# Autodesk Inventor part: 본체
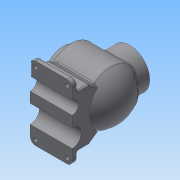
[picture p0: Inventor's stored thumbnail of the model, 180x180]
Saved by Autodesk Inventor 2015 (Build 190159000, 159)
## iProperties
Created: 2018-08
Part Number: 본체
Material: 일반
Document SubType Name: Modeling
Designer: user
Density: 1 g/cm^3
Appearance: 기본값
Mass: 665.121 g
Surface Area: 1060.85 cm^2
Volume: 665.121 cm^3
Author: user
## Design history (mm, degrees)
sketch "스케치1"
  geometry: 1 further point
sketch "스케치2"
  geometry: L1 (0, 0)-(120, 0); L2 (0, 0)-(0, 38); L3 (0, 38)-(12, 38); L4 (12, 38)-(12, 50); L5 (12, 50)-(91.394, 50); A1 r 58 centre (62, 0) between (120, 0) and (91.394, 50)
  constraints: 10 end point, 2 horizontal, 2 perpendicular, 2 point on circle, 1 centre point, 1 horizontal alignment, 1 vertical
  dimensions: "d1" = 38 distance of L1.start L2.end; "d2" = 12 distance of L2.end L3.end; "d7" = 50 distance between parallel lines of L1 L5; "d10" = 116 diameter of A1; "d11" = 108 horizontal distance of L1.end L4.end
revolve "회전1" sketch "스케치2" stored, may be unused: angle "d12" = 90 deg
node "작업 평면1"
sketch "스케치5"
  geometry: L1 (0, 0)-(-82, 0); L2 (-73.171, -50)-(-73.171, -70); L3 (-73.171, -70)-(-83.171, -70); L4 (-83.171, -70)-(-83.171, 70); L5 (-83.171, 70)-(-73.171, 70); L6 (-73.171, 70)-(-73.171, 50); L7 (-73.171, 50)-(-50.839, 50); L8 (-50.839, 50)-(-33.034, 37.533); L9 (-33.034, -37.533)-(-50.839, -50); L10 (-50.839, -50)-(-73.171, -50); A1 r 50 centre (0, 0) between (-33.034, 37.533) and (-33.034, -37.533) reference; A2 r 50 centre (0, 0) between (-33.034, 37.533) and (-33.034, -37.533); 1 further point
  constraints: 20 end point, 4 perpendicular, 4 point on circle, 3 horizontal, 3 horizontal alignment, 1 centre point, 1 coincident, 1 midpoint, 1 vertical alignment, 1 other
  dimensions: "d42" = 82 distance of L1.start L1.end; "d43" = 10 distance of L4.end L5.end; "d44" = 10 distance of L2.end L3.end; "d45" = 140 distance of L3.end L4.end; "d46" = 20 distance of L2.start L2.end; "d47" = 20 distance of L5.end L6.end; "d48" = 35 deg angle of L3 L9
extrude "돌출1" join sketch "스케치5" stored distance "d49" = 80; taper "d50" = 0 deg
sketch "스케치6"
  geometry: L1 (-50, -73.171)-(-70, -73.171) reference; L2 (-70, -73.171)-(-70, -83.171) reference; L3 (-70, -83.171)-(70, -83.171) reference; L4 (70, -83.171)-(70, -73.171) reference; L5 (70, -73.171)-(50, -73.171) reference; L6 (0, 0)-(0, -83.171); C1 r 38 at (0, 0) reference; C2 r 17.5 at (-22.5, -83.171); C3 r 12.5 at (27.5, -83.171); 1 further point
  constraints: 2 centre point, 2 end point, 2 midpoint, 2 point on line, 1 horizontal alignment
  dimensions: "d51" = 35 diameter of C2; "d53" = 22.5 distance of C2.centre L6.end; "d55" = 25 diameter of C3; "d56" = 27.5 distance of C3.centre L6.end
extrude "돌출2" cut sketch "스케치6" stored distance "d57" = 80; taper "d58" = 0 deg
sketch "스케치8"
  geometry: L1 (-12, -50)-(-91.394, -50) reference; L2 (0, 38)-(0, -38) reference; L3 (0, 38)-(0, -38) reference; L4 (-12, 38)-(-12, -38) reference; L5 (-91.394, -37.533)-(-91.394, 37.533) reference; L6 (-91.394, 37.533)-(-91.394, -37.533) reference; L7 (-20, 37.533)-(-91.394, 37.533) reference; L8 (-91.394, -37.533)-(-91.394, 37.533) reference; L9 (-91.394, -37.533)-(-20, -37.533) reference; L10 (-20, -37.533)-(-20, 37.533) reference; L11 (-12, 50)-(-12, -50) reference; C1 r 38 at (-62, 0); 2 further points
  constraints: 1 centre point, 1 horizontal alignment, 1 midpoint
  dimensions: "d59" = 76 diameter of C1; "d60" = 50 distance from line of L4 C1.centre
extrude "돌출3" join sketch "스케치8" distance "d61" = 65; taper "d62" = 0 deg
sketch "스케치9"
  geometry: L1 (0, -38)-(0, 38) reference; L2 (12, -38)-(12, 38) reference; L3 (91.394, 43.818)-(91.394, 43.818) reference; L4 (91.394, 43.818)-(91.394, -33.034) reference; L5 (91.394, -33.034)-(91.394, -33.034) reference; L6 (91.394, -33.034)-(91.394, 43.818) reference; L7 (0, 0)-(110, 0); L8 (0, 0)-(0, 27); L9 (0, 27)-(22, 27); L10 (22, 27)-(22, 40); L11 (22, 40)-(88.533, 40); A1 r 58 centre (62, 0) between (91.394, -50) and (100, 43.818) reference; A2 r 48 centre (62, 0) between (110, 0) and (88.533, 40)
  constraints: 10 end point, 3 perpendicular, 2 point on circle, 1 centre point, 1 horizontal, 1 point on line
  dimensions: "d63" = 27 distance of L7.start L8.end; "d64" = 22 distance of L8.end L9.end; "d65" = 10 radial gap between concentric circles of A1 A2; "d66" = 40 distance between parallel lines of L7 L11
revolve "회전2" sketch "스케치9" stored, may be unused: angle "d67" = 90 deg
sketch "스케치10"
  geometry: C1 r 38 at (0, 0) reference; C2 r 27 at (0, 0); 1 further point
  constraints: 1 centre point, 1 coincident
  dimensions: "d68" = 54 diameter of C2
extrude "돌출4" cut sketch "스케치10" stored distance "d69" = 65; taper "d70" = 0 deg
sketch "스케치11"
  geometry: C1 r 27 at (0, 0) reference; 2 further points
  constraints: 1 horizontal alignment
  dimensions: "d71" = 32.5 distance of point (-32.5, 0) C1.centre
hole "구멍1" sketch "스케치11" at (-32.5, 0) diameter "d72" = 3.242; stored, may be unused: countersink angle "d76" = 90 deg, drill point angle "d78" = 118 deg; dims "d73" = 8, "d74" = 4, "d75" = 2, "d77" = 10
sketch "스케치12"
  geometry: C1 r 27 at (0, 0) reference; 1 further point
  constraints: 1 vertical alignment
  dimensions: "d82" = 32.5 distance of C1.centre point (0, 32.5)
hole "구멍2" sketch "스케치12" at (0, 32.5) diameter "d83" = 3.242; stored, may be unused: countersink angle "d87" = 90 deg, drill point angle "d89" = 118 deg; dims "d84" = 8, "d85" = 4, "d86" = 2, "d88" = 10
sketch "스케치13"
  geometry: L1 (0, 0)-(0, 20) reference; C1 r 4 at (10, 10); C2 r 4 at (70, 10); 2 further points
  constraints: 2 centre point
  dimensions: "d93" = 8 diameter of C1; "d94" = 10 distance from line of L1 C1.centre; "d95" = 10 horizontal distance of L1.end C1.centre; "d96" = 8 diameter of C2; "d97" = 10 horizontal distance of point (80, 20) C2.centre; "d98" = 10 horizontal distance of point (80, 20) C2.centre
extrude "돌출5" cut sketch "스케치13" stored distance "d99" = 65; taper "d100" = 0 deg
node "작업 평면2"
sketch "스케치14"
  geometry: 2 further points
  constraints: 1 horizontal alignment, 1 other
  dimensions: "d103" = 32.5 distance of point (32.5, 0) point (0, 0)
feature "엠보싱1" sketch "스케치14" dims "d1" = 38, "d2" = 12, "d7" = 50, "d10" = 116, "d11" = 108, "d42" = 82, "d43" = 10, "d44" = 10, "d45" = 140, "d46" = 20, "d47" = 20, "d48" = 35 deg, "d104" = 0.5, "d105" = 0
fillet "모깎기1" dims "d106" = 10, "d110" = 3, "d111" = 3, "d112" = 3, "d113" = 3
chamfer "모따기1" distance "d107" = 1; stored, may be unused: second distance "d108" = 2, angle "d109" = 45 deg
node "솔리드1"
pattern_circular "원형 패턴1" dims angle "d80" = 360 deg
pattern_circular "원형 패턴2" dims angle "d91" = 360 deg
mirror "대칭1"
node "투영된 루프2"
node "투영된 루프3"
node "투영된 루프4"
node "투영된 루프5"
node "투영된 루프6"
node "투영된 루프7"
